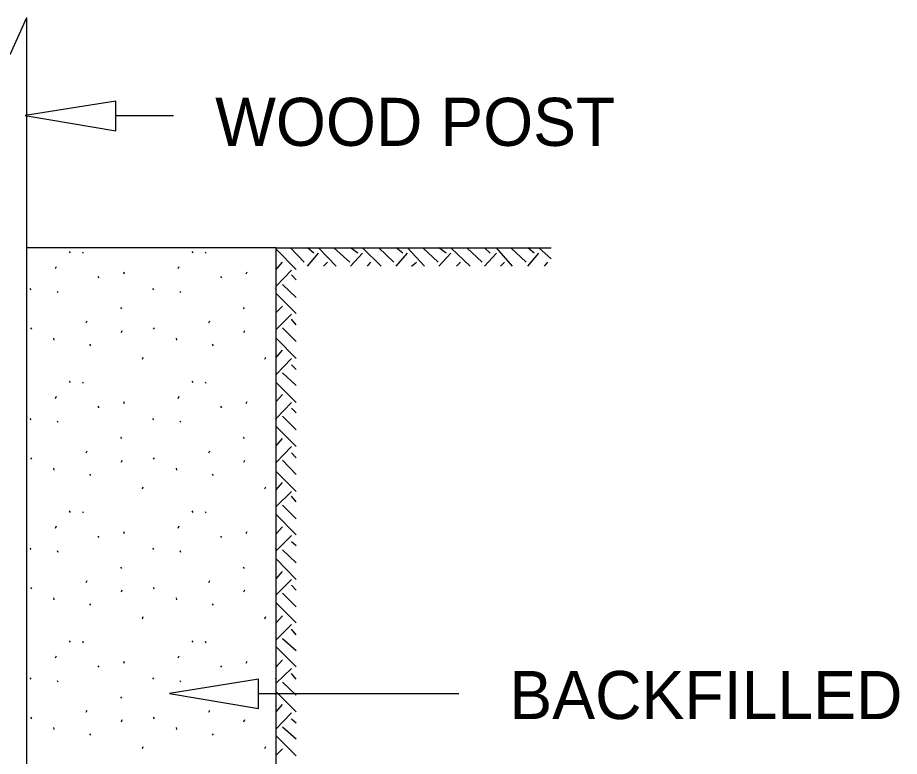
# Model space of a CAD drawing. Extents: x -2137320.7 to -2137313.2, y -2137946.3 to -2137936.1.
# Drawn here: x -2137316.974 to -2137315.873, y -2137937.087 to -2137936.165 of the extents above; entities that cross this region are included whole.
import ezdxf

# ---------------------------------------------------------------- set-up
doc = ezdxf.new("R2010")
doc.units = 0
for name, color, linetype in [('DETL-DIMS', 7, 'Continuous'), ('DETL-LINE', 7, 'Continuous'), ('DETL-NOTE', 7, 'Continuous'), ('DETL-PATT', 7, 'Continuous')]:
    doc.layers.add(name, color=color, linetype=linetype)

msp = doc.modelspace()

# ---------------------------------------------------------------- linework, layer by layer
at = {"layer": 'DETL-DIMS'}
for p, q in [((-2137316.851, -2137936.287), (-2137316.779, -2137936.287)), ((-2137316.673, -2137937.008), (-2137316.423, -2137937.008))]:
    msp.add_line(p, q, dxfattribs=at)
for points in [[(-2137316.851, -2137936.306), (-2137316.851, -2137936.269), (-2137316.964, -2137936.287)], [(-2137316.673, -2137937.027), (-2137316.673, -2137936.99), (-2137316.784, -2137937.008)]]:
    msp.add_lwpolyline(points, close=True, dxfattribs=at)
at = {"layer": 'DETL-LINE'}
for p, q in [((-2137316.983, -2137936.211), (-2137316.962, -2137936.165)), ((-2137316.962, -2137936.455), (-2137316.962, -2137936.165)), ((-2137316.651, -2137936.452), (-2137316.962, -2137936.452)), ((-2137316.962, -2137936.569), (-2137316.962, -2137936.452)), ((-2137316.651, -2137937.533), (-2137316.651, -2137936.452)), ((-2137316.651, -2137936.452), (-2137316.308, -2137936.452)), ((-2137316.962, -2137937.533), (-2137316.962, -2137936.569))]:
    msp.add_line(p, q, dxfattribs=at)
at = {"layer": 'DETL-PATT'}
for p, q in [((-2137316.9091, -2137936.4566), (-2137316.908, -2137936.4584)), ((-2137316.8927, -2137936.4573), (-2137316.8916, -2137936.459)), ((-2137316.7561, -2137936.4566), (-2137316.7549, -2137936.4584)), ((-2137316.7397, -2137936.4573), (-2137316.7385, -2137936.459)), ((-2137316.626, -2137936.479), (-2137316.651, -2137936.454)), ((-2137316.616, -2137936.47), (-2137316.633, -2137936.452)), ((-2137316.604, -2137936.459), (-2137316.612, -2137936.452)), ((-2137316.612, -2137936.475), (-2137316.598, -2137936.459)), ((-2137316.604, -2137936.452), (-2137316.604, -2137936.452)), ((-2137316.576, -2137936.475), (-2137316.598, -2137936.452)), ((-2137316.559, -2137936.47), (-2137316.579, -2137936.452)), ((-2137316.549, -2137936.459), (-2137316.558, -2137936.452)), ((-2137316.558, -2137936.475), (-2137316.543, -2137936.459)), ((-2137316.549, -2137936.452), (-2137316.549, -2137936.452)), ((-2137316.52, -2137936.475), (-2137316.543, -2137936.452)), ((-2137316.504, -2137936.47), (-2137316.523, -2137936.452)), ((-2137316.493, -2137936.459), (-2137316.501, -2137936.452)), ((-2137316.501, -2137936.475), (-2137316.487, -2137936.459)), ((-2137316.493, -2137936.452), (-2137316.493, -2137936.452)), ((-2137316.466, -2137936.475), (-2137316.487, -2137936.452)), ((-2137316.449, -2137936.47), (-2137316.468, -2137936.452)), ((-2137316.439, -2137936.459), (-2137316.448, -2137936.452)), ((-2137316.448, -2137936.475), (-2137316.433, -2137936.459)), ((-2137316.439, -2137936.452), (-2137316.438, -2137936.452)), ((-2137316.409, -2137936.475), (-2137316.433, -2137936.452)), ((-2137316.394, -2137936.47), (-2137316.413, -2137936.452)), ((-2137316.384, -2137936.459), (-2137316.391, -2137936.452)), ((-2137316.391, -2137936.475), (-2137316.376, -2137936.459)), ((-2137316.384, -2137936.452), (-2137316.383, -2137936.452)), ((-2137316.356, -2137936.475), (-2137316.376, -2137936.452)), ((-2137316.339, -2137936.47), (-2137316.358, -2137936.452)), ((-2137316.329, -2137936.459), (-2137316.337, -2137936.452)), ((-2137316.337, -2137936.475), (-2137316.323, -2137936.459)), ((-2137316.329, -2137936.452), (-2137316.326, -2137936.452)), ((-2137316.308, -2137936.466), (-2137316.323, -2137936.452)), ((-2137316.651, -2137936.479), (-2137316.643, -2137936.47)), ((-2137316.592, -2137936.475), (-2137316.587, -2137936.47)), ((-2137316.537, -2137936.475), (-2137316.533, -2137936.47)), ((-2137316.482, -2137936.475), (-2137316.476, -2137936.47)), ((-2137316.426, -2137936.475), (-2137316.421, -2137936.47)), ((-2137316.371, -2137936.475), (-2137316.366, -2137936.47)), ((-2137316.316, -2137936.475), (-2137316.312, -2137936.47)), ((-2137316.9261, -2137936.478), (-2137316.925, -2137936.4754)), ((-2137316.8412, -2137936.4846), (-2137316.8401, -2137936.482)), ((-2137316.7731, -2137936.478), (-2137316.7719, -2137936.4754)), ((-2137316.6882, -2137936.4846), (-2137316.687, -2137936.482)), ((-2137316.651, -2137936.5), (-2137316.632, -2137936.48)), ((-2137316.8734, -2137936.4879), (-2137316.8723, -2137936.4897)), ((-2137316.7204, -2137936.4879), (-2137316.7192, -2137936.4897)), ((-2137316.626, -2137936.492), (-2137316.632, -2137936.486)), ((-2137316.9583, -2137936.503), (-2137316.9572, -2137936.5047)), ((-2137316.9243, -2137936.5061), (-2137316.9232, -2137936.5078)), ((-2137316.8053, -2137936.503), (-2137316.8041, -2137936.5047)), ((-2137316.7713, -2137936.5061), (-2137316.7701, -2137936.5078)), ((-2137316.6522, -2137936.503), (-2137316.6511, -2137936.5047)), ((-2137316.626, -2137936.514), (-2137316.643, -2137936.498)), ((-2137316.626, -2137936.534), (-2137316.651, -2137936.509)), ((-2137316.8451, -2137936.5265), (-2137316.8439, -2137936.5283)), ((-2137316.692, -2137936.5265), (-2137316.6909, -2137936.5283)), ((-2137316.651, -2137936.533), (-2137316.643, -2137936.525)), ((-2137316.651, -2137936.554), (-2137316.632, -2137936.535)), ((-2137316.8879, -2137936.5459), (-2137316.8867, -2137936.5433)), ((-2137316.7348, -2137936.5459), (-2137316.7336, -2137936.5433)), ((-2137316.626, -2137936.548), (-2137316.632, -2137936.541)), ((-2137316.9573, -2137936.5521), (-2137316.9561, -2137936.5538)), ((-2137316.8441, -2137936.5577), (-2137316.843, -2137936.5551)), ((-2137316.8042, -2137936.5521), (-2137316.803, -2137936.5538)), ((-2137316.6911, -2137936.5577), (-2137316.6899, -2137936.5551)), ((-2137316.626, -2137936.569), (-2137316.643, -2137936.552)), ((-2137316.9288, -2137936.5649), (-2137316.9285, -2137936.5675)), ((-2137316.7757, -2137936.5649), (-2137316.7754, -2137936.5675)), ((-2137316.626, -2137936.59), (-2137316.651, -2137936.565)), ((-2137316.8837, -2137936.5725), (-2137316.8825, -2137936.5742)), ((-2137316.7306, -2137936.5725), (-2137316.7295, -2137936.5742)), ((-2137316.651, -2137936.589), (-2137316.643, -2137936.58)), ((-2137316.8179, -2137936.591), (-2137316.8168, -2137936.5885)), ((-2137316.6649, -2137936.591), (-2137316.6637, -2137936.5885)), ((-2137316.651, -2137936.61), (-2137316.632, -2137936.59)), ((-2137316.626, -2137936.604), (-2137316.632, -2137936.598)), ((-2137316.626, -2137936.624), (-2137316.643, -2137936.608)), ((-2137316.9091, -2137936.6185), (-2137316.908, -2137936.6203)), ((-2137316.8927, -2137936.6192), (-2137316.8916, -2137936.6209)), ((-2137316.7561, -2137936.6185), (-2137316.7549, -2137936.6203)), ((-2137316.7397, -2137936.6192), (-2137316.7385, -2137936.6209)), ((-2137316.626, -2137936.645), (-2137316.651, -2137936.62)), ((-2137316.9261, -2137936.6399), (-2137316.925, -2137936.6373)), ((-2137316.7731, -2137936.6399), (-2137316.7719, -2137936.6373)), ((-2137316.651, -2137936.644), (-2137316.643, -2137936.635)), ((-2137316.8412, -2137936.6465), (-2137316.8401, -2137936.6439)), ((-2137316.6882, -2137936.6465), (-2137316.687, -2137936.6439)), ((-2137316.651, -2137936.665), (-2137316.632, -2137936.645)), ((-2137316.8734, -2137936.6498), (-2137316.8723, -2137936.6516)), ((-2137316.7204, -2137936.6498), (-2137316.7192, -2137936.6516)), ((-2137316.626, -2137936.658), (-2137316.632, -2137936.652)), ((-2137316.9583, -2137936.6649), (-2137316.9572, -2137936.6666)), ((-2137316.9243, -2137936.668), (-2137316.9232, -2137936.6697)), ((-2137316.8053, -2137936.6649), (-2137316.8041, -2137936.6666)), ((-2137316.7713, -2137936.668), (-2137316.7701, -2137936.6697)), ((-2137316.6522, -2137936.6649), (-2137316.6511, -2137936.6666)), ((-2137316.626, -2137936.679), (-2137316.643, -2137936.662)), ((-2137316.626, -2137936.7), (-2137316.651, -2137936.675)), ((-2137316.8451, -2137936.6884), (-2137316.8439, -2137936.6902)), ((-2137316.692, -2137936.6884), (-2137316.6909, -2137936.6902)), ((-2137316.651, -2137936.699), (-2137316.643, -2137936.69)), ((-2137316.651, -2137936.72), (-2137316.632, -2137936.7)), ((-2137316.9573, -2137936.714), (-2137316.9561, -2137936.7157)), ((-2137316.8879, -2137936.7078), (-2137316.8867, -2137936.7052)), ((-2137316.8042, -2137936.714), (-2137316.803, -2137936.7157)), ((-2137316.7348, -2137936.7078), (-2137316.7336, -2137936.7052)), ((-2137316.626, -2137936.714), (-2137316.632, -2137936.708)), ((-2137316.8441, -2137936.7196), (-2137316.843, -2137936.717)), ((-2137316.6911, -2137936.7196), (-2137316.6899, -2137936.717)), ((-2137316.626, -2137936.735), (-2137316.643, -2137936.717)), ((-2137316.9288, -2137936.7268), (-2137316.9285, -2137936.7294)), ((-2137316.8837, -2137936.7344), (-2137316.8825, -2137936.7361)), ((-2137316.7757, -2137936.7268), (-2137316.7754, -2137936.7294)), ((-2137316.7306, -2137936.7344), (-2137316.7295, -2137936.7361)), ((-2137316.626, -2137936.756), (-2137316.651, -2137936.731)), ((-2137316.651, -2137936.754), (-2137316.643, -2137936.745)), ((-2137316.8179, -2137936.7529), (-2137316.8168, -2137936.7503)), ((-2137316.6649, -2137936.7529), (-2137316.6637, -2137936.7503)), ((-2137316.651, -2137936.775), (-2137316.632, -2137936.756)), ((-2137316.626, -2137936.769), (-2137316.632, -2137936.762)), ((-2137316.9091, -2137936.7804), (-2137316.908, -2137936.7821)), ((-2137316.8927, -2137936.7811), (-2137316.8916, -2137936.7828)), ((-2137316.7561, -2137936.7804), (-2137316.7549, -2137936.7821)), ((-2137316.7397, -2137936.7811), (-2137316.7385, -2137936.7828)), ((-2137316.626, -2137936.79), (-2137316.643, -2137936.773)), ((-2137316.626, -2137936.81), (-2137316.651, -2137936.785)), ((-2137316.9261, -2137936.8017), (-2137316.925, -2137936.7991)), ((-2137316.7731, -2137936.8017), (-2137316.7719, -2137936.7991)), ((-2137316.651, -2137936.809), (-2137316.643, -2137936.8)), ((-2137316.8734, -2137936.8117), (-2137316.8723, -2137936.8134)), ((-2137316.8412, -2137936.8084), (-2137316.8401, -2137936.8058)), ((-2137316.7204, -2137936.8117), (-2137316.7192, -2137936.8134)), ((-2137316.6882, -2137936.8084), (-2137316.687, -2137936.8058)), ((-2137316.651, -2137936.83), (-2137316.632, -2137936.811)), ((-2137316.626, -2137936.824), (-2137316.632, -2137936.819)), ((-2137316.9583, -2137936.8268), (-2137316.9572, -2137936.8285)), ((-2137316.9243, -2137936.8299), (-2137316.9232, -2137936.8316)), ((-2137316.8053, -2137936.8268), (-2137316.8041, -2137936.8285)), ((-2137316.7713, -2137936.8299), (-2137316.7701, -2137936.8316)), ((-2137316.6522, -2137936.8268), (-2137316.6511, -2137936.8285)), ((-2137316.626, -2137936.845), (-2137316.643, -2137936.829)), ((-2137316.626, -2137936.866), (-2137316.651, -2137936.84)), ((-2137316.8451, -2137936.8503), (-2137316.8439, -2137936.852)), ((-2137316.692, -2137936.8503), (-2137316.6909, -2137936.852)), ((-2137316.651, -2137936.865), (-2137316.643, -2137936.856)), ((-2137316.8879, -2137936.8696), (-2137316.8867, -2137936.8671)), ((-2137316.7348, -2137936.8696), (-2137316.7336, -2137936.8671)), ((-2137316.651, -2137936.885), (-2137316.632, -2137936.866)), ((-2137316.9573, -2137936.8759), (-2137316.9561, -2137936.8776)), ((-2137316.8441, -2137936.8814), (-2137316.843, -2137936.8788)), ((-2137316.8042, -2137936.8759), (-2137316.803, -2137936.8776)), ((-2137316.6911, -2137936.8814), (-2137316.6899, -2137936.8788)), ((-2137316.626, -2137936.879), (-2137316.632, -2137936.873)), ((-2137316.9288, -2137936.8887), (-2137316.9285, -2137936.8913)), ((-2137316.7757, -2137936.8887), (-2137316.7754, -2137936.8913)), ((-2137316.626, -2137936.9), (-2137316.643, -2137936.883)), ((-2137316.8837, -2137936.8963), (-2137316.8825, -2137936.898)), ((-2137316.7306, -2137936.8963), (-2137316.7295, -2137936.898)), ((-2137316.626, -2137936.92), (-2137316.651, -2137936.895)), ((-2137316.8179, -2137936.9148), (-2137316.8168, -2137936.9122)), ((-2137316.6649, -2137936.9148), (-2137316.6637, -2137936.9122)), ((-2137316.651, -2137936.92), (-2137316.643, -2137936.911)), ((-2137316.651, -2137936.941), (-2137316.632, -2137936.922)), ((-2137316.626, -2137936.935), (-2137316.632, -2137936.928)), ((-2137316.9091, -2137936.9423), (-2137316.908, -2137936.944)), ((-2137316.8927, -2137936.943), (-2137316.8916, -2137936.9447)), ((-2137316.7561, -2137936.9423), (-2137316.7549, -2137936.944)), ((-2137316.7397, -2137936.943), (-2137316.7385, -2137936.9447)), ((-2137316.626, -2137936.955), (-2137316.643, -2137936.94)), ((-2137316.626, -2137936.975), (-2137316.651, -2137936.95)), ((-2137316.9261, -2137936.9636), (-2137316.925, -2137936.961)), ((-2137316.8412, -2137936.9702), (-2137316.8401, -2137936.9677)), ((-2137316.7731, -2137936.9636), (-2137316.7719, -2137936.961)), ((-2137316.6882, -2137936.9702), (-2137316.687, -2137936.9677)), ((-2137316.651, -2137936.975), (-2137316.643, -2137936.966)), ((-2137316.8734, -2137936.9736), (-2137316.8723, -2137936.9753)), ((-2137316.7204, -2137936.9736), (-2137316.7192, -2137936.9753)), ((-2137316.651, -2137936.995), (-2137316.632, -2137936.977)), ((-2137316.9583, -2137936.9887), (-2137316.9572, -2137936.9904)), ((-2137316.8053, -2137936.9887), (-2137316.8041, -2137936.9904)), ((-2137316.6522, -2137936.9887), (-2137316.6511, -2137936.9904)), ((-2137316.626, -2137936.99), (-2137316.632, -2137936.983)), ((-2137316.9243, -2137936.9918), (-2137316.9232, -2137936.9935)), ((-2137316.7713, -2137936.9918), (-2137316.7701, -2137936.9935)), ((-2137316.626, -2137937.01), (-2137316.643, -2137936.994)), ((-2137316.8451, -2137937.0122), (-2137316.8439, -2137937.0139)), ((-2137316.626, -2137937.031), (-2137316.651, -2137937.006)), ((-2137316.651, -2137937.031), (-2137316.643, -2137937.022)), ((-2137316.8879, -2137937.0315), (-2137316.8867, -2137937.0289)), ((-2137316.7348, -2137937.0315), (-2137316.7336, -2137937.0289)), ((-2137316.651, -2137937.052), (-2137316.632, -2137937.032)), ((-2137316.9573, -2137937.0377), (-2137316.9561, -2137937.0395)), ((-2137316.8441, -2137937.0433), (-2137316.843, -2137937.0407)), ((-2137316.8042, -2137937.0377), (-2137316.803, -2137937.0395)), ((-2137316.6911, -2137937.0433), (-2137316.6899, -2137937.0407)), ((-2137316.626, -2137937.045), (-2137316.632, -2137937.04)), ((-2137316.9288, -2137937.0505), (-2137316.9285, -2137937.0531)), ((-2137316.7757, -2137937.0505), (-2137316.7754, -2137937.0531)), ((-2137316.626, -2137937.065), (-2137316.643, -2137937.05)), ((-2137316.8837, -2137937.0582), (-2137316.8825, -2137937.0599)), ((-2137316.7306, -2137937.0582), (-2137316.7295, -2137937.0599)), ((-2137316.626, -2137937.086), (-2137316.651, -2137937.061)), ((-2137316.8179, -2137937.0767), (-2137316.8168, -2137937.0741)), ((-2137316.6649, -2137937.0767), (-2137316.6637, -2137937.0741)), ((-2137316.651, -2137937.085), (-2137316.643, -2137937.077))]:
    msp.add_line(p, q, dxfattribs=at)

# ---------------------------------------------------------------- texts
at = {"layer": 'DETL-NOTE'}
for s, p in [('WOOD POST', (-2137316.727, -2137936.325)), ('BACKFILLED', (-2137316.36, -2137937.04))]:
    msp.add_text(s, height=0.06, dxfattribs=at).set_placement(p)

doc.saveas('drawing.dxf')
